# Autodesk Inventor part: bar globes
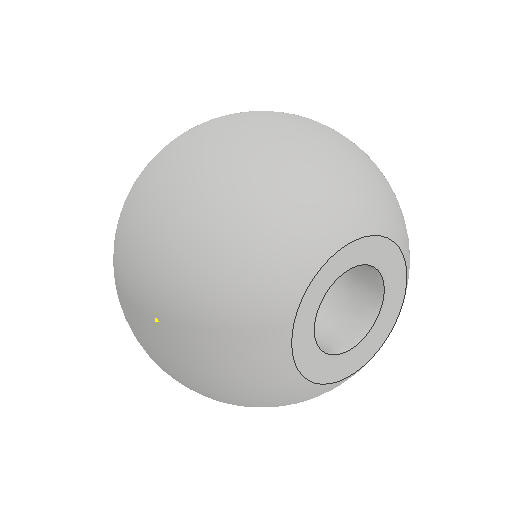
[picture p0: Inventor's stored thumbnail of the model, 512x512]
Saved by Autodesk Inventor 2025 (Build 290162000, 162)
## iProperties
Created: 2016-03
Part Number: bar globes
Material: Generic
Document SubType Name: Modeling
Designer: Sandeep
Density: 1 g/cm^3
Appearance: Default
Mass: 0.753654 g
Surface Area: 5.66286 cm^2
Volume: 0.753654 cm^3
Author: Sandeep
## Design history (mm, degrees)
sketch "Sketch1"
  geometry: L1 (0, 12)-(0, 0); A1 r 6 centre (0, 6) between (0, 12) and (0, 0)
  constraints: 2 end point, 2 point on circle, 1 centre point, 1 midpoint, 1 vertical
revolve "Revolution1" sketch "Sketch1" stored, may be unused: angle "d1" = 90 deg
sketch "Sketch5"
  geometry: L1 (5.014, 9.295)-(5.014, 2.705); A1 r 6 centre (0, 6) between (0, 0) and (5.014, 9.295) reference; A2 r 6 centre (0, 6) between (0, 0) and (5.014, 2.705) reference; 2 further points
  constraints: 2 end point, 2 point on circle, 1 vertical, 1 vertical alignment
extrude "Extrusion1" cut sketch "Sketch5" stored distance "d2" = 10; taper "d3" = 0 deg
sketch "Sketch6"
  geometry: L1 (5.65, 4.164)-(5.65, -4.091); A1 r 6 centre (0, 0) between (-5.014, -3.295) and (-5.014, 3.295) reference; 1 further point
  constraints: 2 end point, 1 vertical
extrude "Extrusion2" cut sketch "Sketch6" distance "d5" = 15.75; taper "d6" = 0 deg
sketch "Sketch7"
  geometry: L1 (-5.65, 3.981)-(-5.65, 8.019) reference; L2 (-5.65, 6)-(5.014, 6); L3 (-4.986, 8)-(5.014, 8); L4 (5.014, 8)-(5.014, 6); L5 (5.014, 9.295)-(5.014, 2.705) reference; L6 (-5.65, 7.336)-(-5.65, 6); L7 (-4.986, 8)-(-5.65, 7.336); 3 further points
  constraints: 10 end point, 2 collinear, 2 horizontal, 2 midpoint, 2 point on line
  dimensions: "d16" = 4 diameter of L3 L2; "d17" = 10 distance of L3.end L3.start; "d19" = 45 deg angle of L7 L3
revolve "Revolution2" sketch "Sketch7" stored, may be unused: angle "d18" = 90 deg
body "Solid1"
sketch "Sketch2"
  geometry: 1 further point
sketch "Sketch3"
  geometry: 1 further point
sketch "Sketch4"
  geometry: 1 further point
other parameters: "d4" = 15.75
